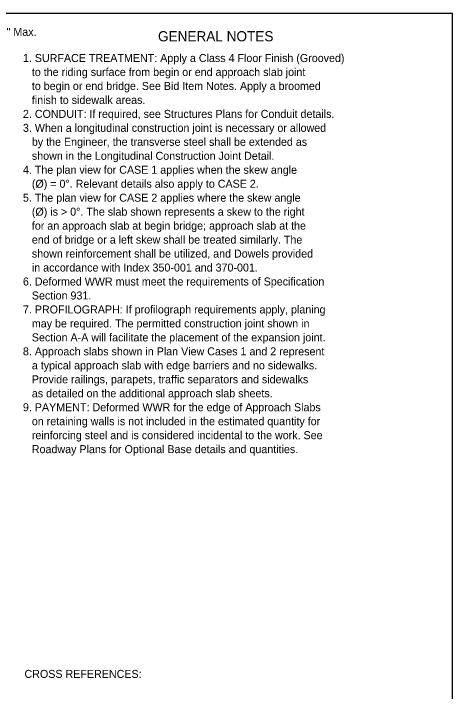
# Model space of a CAD drawing. Extents: x 122756 to 123150, y 88002 to 88156.
# Drawn here: x 122885.9 to 122930.2, y 88072.6 to 88140.9 of the extents above; entities that cross this region are included whole.
import ezdxf

# ---------------------------------------------------------------- set-up
doc = ezdxf.new("R2010")
doc.units = 0
for name, color, linetype in [('ActivePts-ConstElements', 7, 'Continuous'), ('Border', 7, 'Continuous'), ('Patterning', 7, 'Continuous')]:
    doc.layers.add(name, color=color, linetype=linetype)

msp = doc.modelspace()

# ---------------------------------------------------------------- linework, layer by layer
at = {"layer": 'ActivePts-ConstElements'}
msp.add_lwpolyline([(122765.929, 88035.339), (122930.195, 88035.339), (122930.195, 88140.939), (122765.929, 88140.939)], close=True, dxfattribs=at)

# ---------------------------------------------------------------- texts
at = {"layer": 'Border'}
msp.add_text('GENERAL NOTES', height=1.024, dxfattribs=at).set_placement((122900.506, 88138.14))
at = {"layer": 'Patterning'}
for s, p in [('Varies 1\'-6" Max.', (122880.125, 88138.689)), ('1. SURFACE TREATMENT: Apply a Class 4 Floor Finish (Grooved) ', (122886.891, 88136.054)), ('   to the riding surface from begin or end approach slab joint ', (122886.891, 88134.646)), ('   to begin or end bridge. See Bid Item Notes. Apply a broomed ', (122886.891, 88133.238)), ('   finish to sidewalk areas.', (122886.891, 88131.83)), ('2. CONDUIT: If required, see Structures Plans for Conduit details.  ', (122886.891, 88130.422)), ('3. When a longitudinal construction joint is necessary or allowed ', (122886.891, 88129.014)), ('   by the Engineer, the transverse steel shall be extended as ', (122886.891, 88127.606)), ('   shown in the Longitudinal Construction Joint Detail.', (122886.891, 88126.198)), ('4. The plan view for CASE 1 applies when the skew angle ', (122886.891, 88124.79)), ('   (Ø) = 0°. Relevant details also apply to CASE 2.    ', (122886.891, 88123.382)), ('5. The plan view for CASE 2 applies where the skew angle ', (122886.891, 88121.974)), ('   (Ø) is > 0°. The slab shown represents a skew to the right', (122886.891, 88120.566)), ('   for an approach slab at begin bridge; approach slab at the ', (122886.891, 88119.158)), ('   end of bridge or a left skew shall be treated similarly. The ', (122886.891, 88117.75)), ('   shown reinforcement shall be utilized, and Dowels provided', (122886.891, 88116.342)), ('   in accordance with Index 350-001 and 370-001.', (122886.891, 88114.934)), ('6. Deformed WWR must meet the requirements of Specification', (122886.891, 88113.526)), ('   Section 931.', (122886.891, 88112.118)), ('7. PROFILOGRAPH: If profilograph requirements apply, planing ', (122886.891, 88110.71)), ('   may be required. The permitted construction joint shown in ', (122886.891, 88109.302)), ('   Section A-A will facilitate the placement of the expansion joint.', (122886.891, 88107.894)), ('8. Approach slabs shown in Plan View Cases 1 and 2 represent ', (122886.891, 88106.486)), ('   a typical approach slab with edge barriers and no sidewalks. ', (122886.891, 88105.078)), ('   Provide railings, parapets, traffic separators and sidewalks', (122886.891, 88103.67)), ('   as detailed on the additional approach slab sheets.', (122886.891, 88102.262)), ('9. PAYMENT: Deformed WWR for the edge of Approach Slabs', (122886.891, 88100.854)), ('   on retaining walls is not included in the estimated quantity for', (122886.891, 88099.446)), ('   reinforcing steel and is considered incidental to the work. See', (122886.891, 88098.038)), ('   Roadway Plans for Optional Base details and quantities.', (122886.891, 88096.63)), ('CROSS REFERENCES:', (122887.049, 88073.976))]:
    msp.add_text(s, height=0.8064, dxfattribs=at).set_placement(p)

doc.saveas('drawing.dxf')
